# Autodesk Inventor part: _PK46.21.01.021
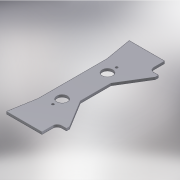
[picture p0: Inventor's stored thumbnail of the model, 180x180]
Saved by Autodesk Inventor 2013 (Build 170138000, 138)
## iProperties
Created: 2005-04
Part Number: _PK46.21.01.021
Material: Steel, Mild
Document SubType Name: Modeling
Designer: salex
Manufacturer: Standard
Standards Organization: Custom
Density: 7.86 g/cm^3
Author: salex
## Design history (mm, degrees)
sketch "Эскиз1"
  geometry: L1 (0, 0)-(378.386, 0); L2 (0, -225)-(0, 225); L3 (0, 225)-(-30, 400); L4 (-30, 400)-(200, 400); L5 (200, 400)-(200, 280); L6 (200, 280)-(150, 100); L7 (150, 100)-(150, -100); L8 (200, -280)-(150, -100); L9 (0, -225)-(-30, -400); L10 (-30, -400)-(200, -400); L11 (200, -400)-(200, -280); C1 r 35 at (80, 148); C2 r 8 at (80, 208); C3 r 35 at (80, -148); C4 r 8 at (80, -208)
  constraints: 22 end point, 7 symmetric about line, 4 centre point, 3 perpendicular, 1 horizontal, 1 parallel, 3 other
  dimensions: "d0" = 0 distance from line of L1.start L2; "d1" = 800 diameter of L4 L1; "d2" = 450 diameter of L2.end L1; "d3" = 200 diameter of L6.end L1; "d4" = 120 distance of L4.end L5.end; "d5" = 120 distance from line of L5 C1.centre; "d6" = 60 distance of C2.centre C1.centre; "d7" = 296 diameter of C1.centre L1; "d8" = 0 horizontal distance of C1.centre C2.centre; "d9" = 70 diameter of C1; "d10" = 16 diameter of C2; "d11" = 230 distance of L3.end L4.end; "d12" = 50 distance between parallel lines of L5 L7; "d16" = 150 distance between parallel lines of L7 L2
extrude "Выдавливание1" new body sketch "Эскиз1" distance "d14" = 16; taper "d15" = 0 deg
sketch "Эскиз2"
  geometry: L1 (150, 100)-(150, -100) reference; L2 (200, 280)-(150, 100) reference; L3 (200, 400)-(200, 280) reference; L4 (-30, 400)-(200, 400) reference; L5 (150, 100)-(260, 280); L6 (260, 280)-(260, 300); L7 (260, 300)-(230, 300); A1 r 30 centre (230, 330) between (200, 330) and (230, 300)
  constraints: 6 end point, 2 perpendicular, 2 point on circle, 2 tangent, 1 centre point, 1 point on line
  dimensions: "d17" = 100 distance between parallel lines of L4 L7; "d18" = 30 radius of A1; "d19" = 120 distance from line of L5.end L4; "d20" = 110 distance between parallel lines of L6 L1
extrude "Выдавливание2" join sketch "Эскиз2" stored distance "d21" = 10; taper "d22" = 0 deg
mirror "ЗеркОтобр1"
sketch "Эскиз3"
  geometry: L1 (150, 100)-(260, 280) reference; L2 (260, 280)-(260, 300) reference; L3 (260, 300)-(230, 300) reference; L4 (170.089, 257.031)-(250, 285) reference; L5 (250, 285)-(250, 300) reference; L6 (150, 100)-(163.158, 235.965) reference; A1 r 30 centre (180, 228.716) between (170.089, 257.031) and (150, 228.716) reference
extrude "Выдавливание3" cut sketch "Эскиз3" stored distance "d24" = 10; taper "d25" = 0 deg
body "Solid1"
node "ЗаимстЛин1"
node "ЗаимстЛин2"
node "ЗаимстЛин3"
node "ЗаимстЛин4"
